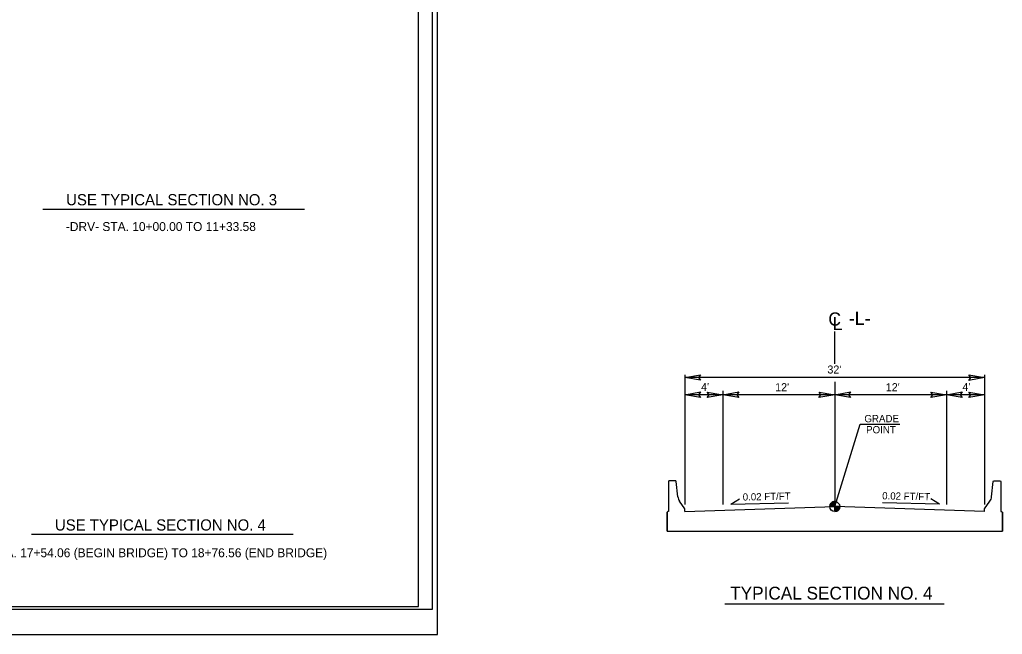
# Model space of a CAD drawing. Extents: x 1718167 to 1721223, y 797898 to 799800.
# Drawn here: x 1720176 to 1721055, y 798024 to 798574 of the extents above; entities that cross this region are included whole.
import ezdxf

# ---------------------------------------------------------------- set-up
doc = ezdxf.new("R2010")
doc.units = 0
for name, color, linetype in [('Default', 7, 'Continuous'), ('Old_Level_1', 7, 'Continuous'), ('Old_Level_18', 7, 'Continuous'), ('Old_Level_2', 7, 'Continuous'), ('Prop Shade Heavy', 7, 'Continuous'), ('Sheet Cutting Line CELL', 7, 'Continuous'), ('Sheet Plot Border Inside CELL', 7, 'Continuous'), ('Sheet Plot Border Outside CELL', 7, 'Continuous'), ('Sheet Typical CELL', 7, 'Continuous'), ('Typical Bridge Rail CELL', 7, 'Continuous'), ('Typical Grade Point Symbol CELL', 7, 'Continuous'), ('Typical Pavement Slope CELL', 7, 'Continuous'), ('Typical Pavement Slope Information CELL', 7, 'Continuous'), ('Typical Terminator CELL', 7, 'Continuous'), ('Typical Text Centerline CELL', 7, 'Continuous'), ('Typical Text Grade Point CELL', 7, 'Continuous'), ('Typical Text Label CELL', 7, 'Continuous')]:
    doc.layers.add(name, color=color, linetype=linetype)

msp = doc.modelspace()

# ---------------------------------------------------------------- linework, layer by layer
at = {"layer": 'Default'}
for p, q in [((1720196.64, 798404.88), (1720431, 798404.88)), ((1720186.53, 798113.86), (1720420.89, 798113.86))]:
    msp.add_line(p, q, dxfattribs=at)
at = {"layer": 'Old_Level_1'}
for p, q in [((1720805.45, 798238.77), (1720771.28, 798238.77)), ((1720905.45, 798238.77), (1720805.45, 798238.77)), ((1721005.45, 798238.77), (1720905.45, 798238.77)), ((1721002.18, 798238.77), (1721000.45, 798238.77)), ((1721039.62, 798238.77), (1721005.45, 798238.77)), ((1720755.45, 798133.55), (1720755.45, 798116.69)), ((1721055.45, 798133.55), (1721055.45, 798116.69)), ((1721055.45, 798133.55), (1721055.45, 798116.7)), ((1720755.45, 798116.69), (1721055.45, 798116.69))]:
    msp.add_line(p, q, dxfattribs=at)
at = {"layer": 'Old_Level_18'}
for p, q in [((1720755.45, 798116.69), (1720755.45, 798133.56)), ((1721055.45, 798116.69), (1721055.45, 798133.55))]:
    msp.add_line(p, q, dxfattribs=at)
at = {"layer": 'Old_Level_2'}
for p, q in [((1720905.45, 798285.61), (1720905.45, 798295.21)), ((1720905.45, 798266.36), (1720905.45, 798285.61)), ((1720771.29, 798256.59), (1720771.29, 798140.57)), ((1721039.62, 798256.51), (1721039.62, 798140.57)), ((1721039.62, 798254.09), (1720771.29, 798254.09)), ((1720905.45, 798250.45), (1720905.45, 798135.53)), ((1720805.45, 798242.22), (1720805.45, 798140.57)), ((1721005.45, 798242.22), (1721005.45, 798140.57)), ((1720905.45, 798138.68), (1720928.3, 798212.55))]:
    msp.add_line(p, q, dxfattribs=at)
at = {"layer": 'Prop Shade Heavy'}
msp.add_line((1720905.45, 798139.72), (1720905.45, 798138.68), dxfattribs=at)
at = {"layer": 'Sheet Cutting Line CELL'}
msp.add_line((1718866, 798024.37), (1720550, 798024.37), dxfattribs=at)
at = {"layer": 'Sheet Plot Border Inside CELL'}
msp.add_lwpolyline([(1720545.5, 799101.92), (1718879, 799101.92), (1718879, 798046.82), (1720545.5, 798046.82)], close=True, dxfattribs=at)
at = {"layer": 'Sheet Plot Border Outside CELL'}
msp.add_lwpolyline([(1720550, 799124.37), (1718866, 799124.37), (1718866, 798024.37), (1720550, 798024.37)], close=True, dxfattribs=at)
at = {"layer": 'Sheet Typical CELL'}
msp.add_lwpolyline([(1720533, 799099.37), (1719033, 799099.37), (1719033, 798049.37), (1720533, 798049.37)], close=True, dxfattribs=at)
at = {"layer": 'Typical Bridge Rail CELL'}
for p, q in [((1720757.06, 798161.59), (1720756.74, 798161.27)), ((1720756.74, 798161.27), (1720756.74, 798134.2)), ((1720763.26, 798161.59), (1720757.06, 798161.59)), ((1720763.62, 798161.23), (1720763.26, 798161.59)), ((1720765.06, 798147.53), (1720763.62, 798161.23)), ((1721045.84, 798147.52), (1721047.28, 798161.22)), ((1721047.28, 798161.22), (1721047.64, 798161.58)), ((1721047.64, 798161.58), (1721053.85, 798161.58)), ((1721053.85, 798161.58), (1721054.17, 798161.26)), ((1721054.17, 798161.26), (1721054.17, 798134.19)), ((1720771.29, 798136.77), (1720766.56, 798143.52)), ((1721039.62, 798136.76), (1721044.34, 798143.51)), ((1720756.09, 798134.2), (1720755.45, 798133.56)), ((1720755.45, 798133.56), (1720755.45, 798129.07)), ((1720756.74, 798134.2), (1720756.09, 798134.2)), ((1720771.29, 798134.21), (1720771.29, 798136.77)), ((1721039.62, 798134.19), (1721039.62, 798136.76)), ((1721054.17, 798134.19), (1721054.81, 798134.19)), ((1721054.81, 798134.19), (1721055.45, 798133.55)), ((1721055.45, 798133.55), (1721055.45, 798129.06))]:
    msp.add_line(p, q, dxfattribs=at)
for centre, start, end in [((1720773.57, 798148.43), 186.01107, 214.9913), ((1721037.33, 798148.42), 325.0087, 353.98893)]:
    msp.add_arc(centre, 8.56, start, end, dxfattribs=at)
at = {"layer": 'Typical Grade Point Symbol CELL'}
for p, q in [((1720905.45, 798138.68), (1720905.45, 798143.18)), ((1720900.95, 798138.68), (1720905.45, 798138.68)), ((1720905.46, 798134.18), (1720905.45, 798138.68)), ((1720909.95, 798138.68), (1720905.45, 798138.68)), ((1720905.45, 798138.68), (1720905.46, 798134.18))]:
    msp.add_line(p, q, dxfattribs=at)
for points in [[(1720901.81, 798141.32), (1720901.81, 798138.68)], [(1720901.9, 798141.44), (1720901.9, 798138.68)], [(1720901.99, 798141.55), (1720901.99, 798138.68)], [(1720902.08, 798141.66), (1720902.08, 798138.68)], [(1720902.17, 798141.76), (1720902.17, 798138.68)], [(1720902.26, 798141.85), (1720902.26, 798138.68)], [(1720902.35, 798141.94), (1720902.35, 798138.68)], [(1720902.44, 798142.02), (1720902.44, 798138.68)], [(1720902.53, 798142.1), (1720902.53, 798138.68)], [(1720902.62, 798142.18), (1720902.62, 798138.68)], [(1720902.71, 798142.25), (1720902.71, 798138.68)], [(1720902.8, 798142.31), (1720902.8, 798138.68)], [(1720902.89, 798142.38), (1720902.89, 798138.68)], [(1720902.98, 798142.44), (1720902.98, 798138.68)], [(1720903.07, 798142.5), (1720903.07, 798138.68)], [(1720903.16, 798142.55), (1720903.16, 798138.68)], [(1720903.25, 798142.6), (1720903.25, 798138.68)], [(1720903.34, 798142.65), (1720903.34, 798138.68)], [(1720903.43, 798142.7), (1720903.43, 798138.68)], [(1720903.52, 798142.74), (1720903.52, 798138.68)], [(1720903.61, 798142.78), (1720903.61, 798138.68)], [(1720903.7, 798142.82), (1720903.7, 798138.68)], [(1720903.79, 798142.86), (1720903.79, 798138.68)], [(1720903.88, 798142.9), (1720903.88, 798138.68)], [(1720903.97, 798142.93), (1720903.97, 798138.68)], [(1720904.06, 798142.96), (1720904.06, 798138.68)], [(1720904.15, 798142.99), (1720904.15, 798138.68)], [(1720904.24, 798143.01), (1720904.24, 798138.68)], [(1720904.33, 798143.04), (1720904.33, 798138.68)], [(1720904.42, 798143.06), (1720904.42, 798138.68)], [(1720904.51, 798143.08), (1720904.51, 798138.68)], [(1720904.6, 798143.1), (1720904.6, 798138.68)], [(1720904.69, 798143.12), (1720904.69, 798138.68)], [(1720904.78, 798143.13), (1720904.78, 798138.68)], [(1720904.87, 798143.14), (1720904.87, 798138.68)], [(1720904.96, 798143.15), (1720904.96, 798138.68)], [(1720905.05, 798143.16), (1720905.05, 798138.68)], [(1720905.14, 798143.17), (1720905.14, 798138.68)], [(1720905.23, 798143.17), (1720905.23, 798138.68)], [(1720905.32, 798143.18), (1720905.32, 798138.68)], [(1720905.41, 798143.18), (1720905.41, 798143.18), (1720905.41, 798138.68)], [(1720901, 798139.32), (1720901, 798138.68)], [(1720901.09, 798139.78), (1720901.09, 798138.68)], [(1720901.18, 798140.09), (1720901.18, 798138.68)], [(1720901.27, 798140.34), (1720901.27, 798138.68)], [(1720901.36, 798140.55), (1720901.36, 798138.68)], [(1720901.45, 798140.74), (1720901.45, 798138.68)], [(1720901.54, 798140.9), (1720901.54, 798138.68)], [(1720901.63, 798141.05), (1720901.63, 798138.68)], [(1720901.72, 798141.19), (1720901.72, 798138.68)], [(1720905.52, 798138.68), (1720905.52, 798134.18), (1720905.52, 798134.18)], [(1720905.61, 798138.68), (1720905.61, 798134.18)], [(1720905.7, 798138.68), (1720905.7, 798134.19)], [(1720905.79, 798138.68), (1720905.79, 798134.19)], [(1720905.88, 798138.68), (1720905.88, 798134.2)], [(1720905.97, 798138.68), (1720905.97, 798134.21)], [(1720906.06, 798138.68), (1720906.06, 798134.22)], [(1720906.15, 798138.68), (1720906.15, 798134.24)], [(1720906.24, 798138.68), (1720906.24, 798134.25)], [(1720906.33, 798138.68), (1720906.33, 798134.27)], [(1720906.42, 798138.68), (1720906.42, 798134.29)], [(1720906.51, 798138.68), (1720906.51, 798134.31)], [(1720906.6, 798138.68), (1720906.6, 798134.33)], [(1720906.69, 798138.68), (1720906.69, 798134.36)], [(1720906.78, 798138.68), (1720906.78, 798134.38)], [(1720906.87, 798138.68), (1720906.87, 798134.41)], [(1720906.96, 798138.68), (1720906.96, 798134.44)], [(1720907.05, 798138.68), (1720907.05, 798134.47)], [(1720907.14, 798138.68), (1720907.14, 798134.51)], [(1720907.23, 798138.68), (1720907.23, 798134.55)], [(1720907.32, 798138.68), (1720907.32, 798134.59)], [(1720907.41, 798138.68), (1720907.41, 798134.63)], [(1720907.5, 798138.68), (1720907.5, 798134.67)], [(1720907.59, 798138.68), (1720907.59, 798134.72)], [(1720907.68, 798138.68), (1720907.68, 798134.77)], [(1720907.77, 798138.68), (1720907.77, 798134.82)], [(1720907.86, 798138.68), (1720907.86, 798134.88)], [(1720907.95, 798138.68), (1720907.95, 798134.94)], [(1720908.04, 798138.68), (1720908.04, 798135)], [(1720908.13, 798138.68), (1720908.13, 798135.06)], [(1720908.22, 798138.68), (1720908.22, 798135.13)], [(1720908.31, 798138.68), (1720908.31, 798135.2)], [(1720908.4, 798138.68), (1720908.4, 798135.28)], [(1720908.49, 798138.68), (1720908.49, 798135.36)], [(1720908.58, 798138.68), (1720908.58, 798135.44)], [(1720908.67, 798138.68), (1720908.67, 798135.53)], [(1720908.76, 798138.68), (1720908.76, 798135.63)], [(1720908.85, 798138.68), (1720908.85, 798135.73)], [(1720908.94, 798138.68), (1720908.94, 798135.84)], [(1720909.03, 798138.68), (1720909.03, 798135.95)], [(1720909.12, 798138.68), (1720909.12, 798136.07)], [(1720909.21, 798138.68), (1720909.21, 798136.2)], [(1720909.3, 798138.68), (1720909.3, 798136.34)], [(1720909.39, 798138.68), (1720909.39, 798136.5)], [(1720909.48, 798138.68), (1720909.48, 798136.67)], [(1720909.57, 798138.68), (1720909.57, 798136.86)], [(1720909.66, 798138.68), (1720909.66, 798137.07)], [(1720909.75, 798138.68), (1720909.75, 798137.34)], [(1720909.84, 798138.68), (1720909.84, 798137.66)], [(1720909.93, 798138.68), (1720909.93, 798138.19)]]:
    msp.add_lwpolyline(points, dxfattribs=at)
msp.add_circle((1720905.45, 798138.68), 4.5, dxfattribs=at)
for start, end in [(90.00952, 180.00952), (270.00952, 0.00952)]:
    msp.add_arc((1720905.45, 798138.68), 4.5, start, end, dxfattribs=at)
at = {"layer": 'Typical Pavement Slope CELL'}
for p in [(1720771.29, 798134.21), (1721039.62, 798134.19)]:
    msp.add_line(p, (1720905.45, 798138.68), dxfattribs=at)
at = {"layer": 'Typical Pavement Slope Information CELL'}
for p, q in [((1720812.49, 798140.96), (1720820.32, 798145.7)), ((1720812.49, 798140.96), (1720864.12, 798142)), ((1720999.18, 798140.98), (1720948.32, 798142)), ((1720999.18, 798140.98), (1720991.35, 798145.72))]:
    msp.add_line(p, q, dxfattribs=at)
at = {"layer": 'Typical Terminator CELL'}
for points in [[(1720785.35, 798251.67), (1720771.29, 798254.09), (1720785.42, 798256.59), (1720783.63, 798254.09)], [(1721025.56, 798256.51), (1721039.62, 798254.09), (1721025.48, 798251.59), (1721027.28, 798254.09)], [(1720785.34, 798236.35), (1720771.28, 798238.77), (1720785.42, 798241.27), (1720783.62, 798238.77)], [(1720791.39, 798241.2), (1720805.45, 798238.77), (1720791.31, 798236.27), (1720793.11, 798238.77)], [(1720819.51, 798236.35), (1720805.45, 798238.77), (1720819.59, 798241.27), (1720817.79, 798238.77)], [(1720891.39, 798241.2), (1720905.45, 798238.77), (1720891.31, 798236.27), (1720893.11, 798238.77)], [(1720919.51, 798236.35), (1720905.45, 798238.77), (1720919.59, 798241.27), (1720917.79, 798238.77)], [(1720991.39, 798241.2), (1721005.45, 798238.77), (1720991.31, 798236.27), (1720993.11, 798238.77)], [(1721019.51, 798236.35), (1721005.45, 798238.77), (1721019.59, 798241.27), (1721017.79, 798238.77)], [(1721025.56, 798241.2), (1721039.62, 798238.77), (1721025.48, 798236.27), (1721027.28, 798238.77)]]:
    msp.add_lwpolyline(points, close=True, dxfattribs=at)
at = {"layer": 'Typical Text Grade Point CELL'}
msp.add_line((1720928.3, 798212.55), (1720963.68, 798212.55), dxfattribs=at)
at = {"layer": 'Typical Text Label CELL'}
msp.add_line((1720807.11, 798051.6), (1721003.38, 798051.6), dxfattribs=at)

# ---------------------------------------------------------------- texts
at = {"layer": 'Default'}
for s, height, p in [('USE TYPICAL SECTION NO. 3', 10, (1720217.65, 798408.27)), ('-DRV- STA. 10+00.00 TO 11+33.58', 8, (1720217.38, 798385.23)), ('USE TYPICAL SECTION NO. 4', 10, (1720207.6, 798117.25)), ('-L- STA. 17+54.06 (BEGIN BRIDGE) TO 18+76.56 (END BRIDGE)', 8, (1720133.7, 798093.36))]:
    msp.add_text(s, height=height, dxfattribs=at).set_placement(p)
at = {"layer": 'Old_Level_1'}
for s, p in [("32'", (1720898.89, 798257.76)), ("4'", (1720785.85, 798242.15)), ("12'", (1720852.16, 798241.94)), ("12'", (1720951.15, 798241.94)), ("4'", (1721019.7, 798242.15))]:
    msp.add_text(s, height=7.161, rotation=360, dxfattribs=at).set_placement(p)
at = {"layer": 'Old_Level_2'}
for rotation, p in [(1.20298, (1720823.19, 798144.02)), (358.79702, (1720947.86, 798145.17))]:
    msp.add_text('0.02 FT/FT', height=6.476, rotation=rotation, dxfattribs=at).set_placement(p)
at = {"layer": 'Typical Text Centerline CELL'}
msp.add_text('C', height=11.82, dxfattribs=at).set_placement((1720899.7, 798300.6))
msp.add_text('L', height=11.82, rotation=359.9469, dxfattribs=at).set_placement((1720903.63, 798296.57))
at = {"layer": 'Typical Text Grade Point CELL'}
for s, height, p in [('-L-', 12, (1720917.97, 798301.21)), ('GRADE', 6.525, (1720931.94, 798214.11)), ('POINT', 6.525, (1720933.51, 798204.22))]:
    msp.add_text(s, height=height, dxfattribs=at).set_placement(p)
at = {"layer": 'Typical Text Label CELL'}
msp.add_text('TYPICAL SECTION NO. 4', height=11.5, dxfattribs=at).set_placement((1720811.87, 798055.49))

doc.saveas('drawing.dxf')
